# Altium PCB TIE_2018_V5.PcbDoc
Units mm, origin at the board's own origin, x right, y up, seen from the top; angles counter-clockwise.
Board outline 31 x 99 mm, 4 copper layers (T, IN1, IN2, B), stack 0.558 mm thick; 52 components, 39 nets, 169 pads, 161 vias.
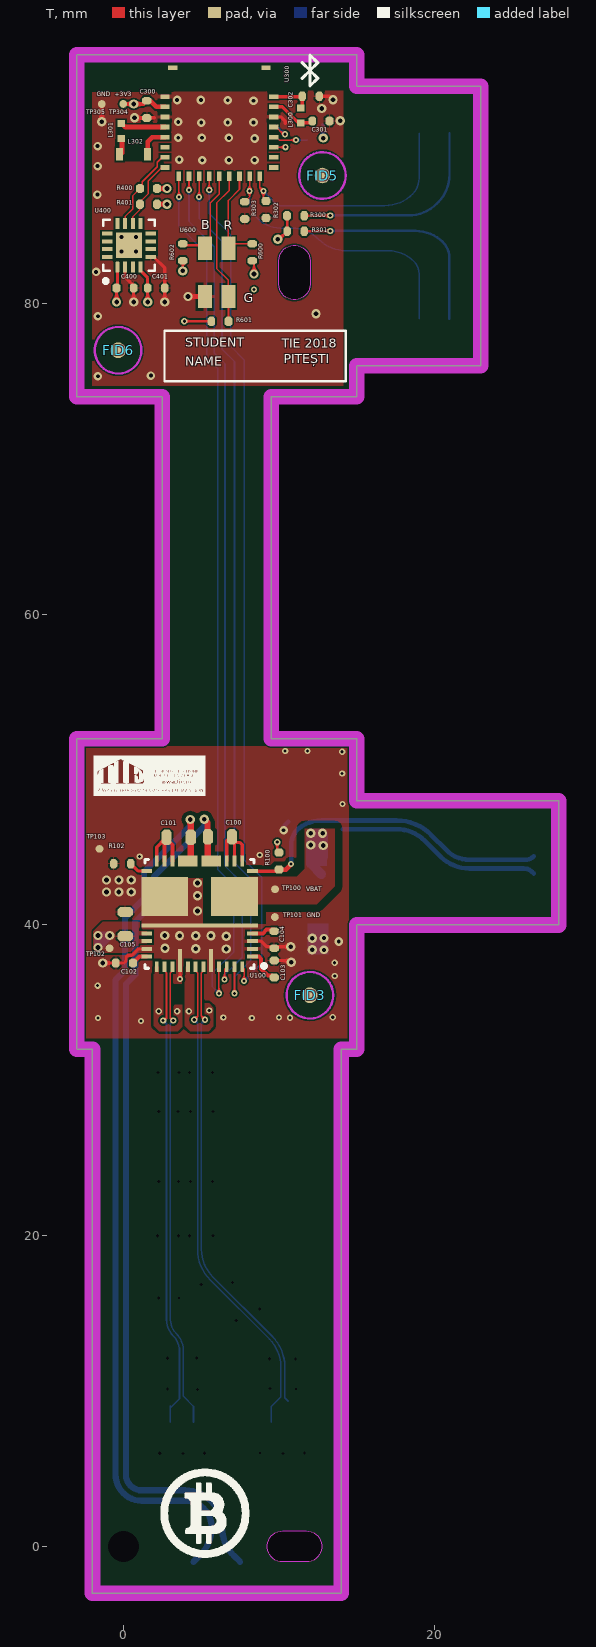
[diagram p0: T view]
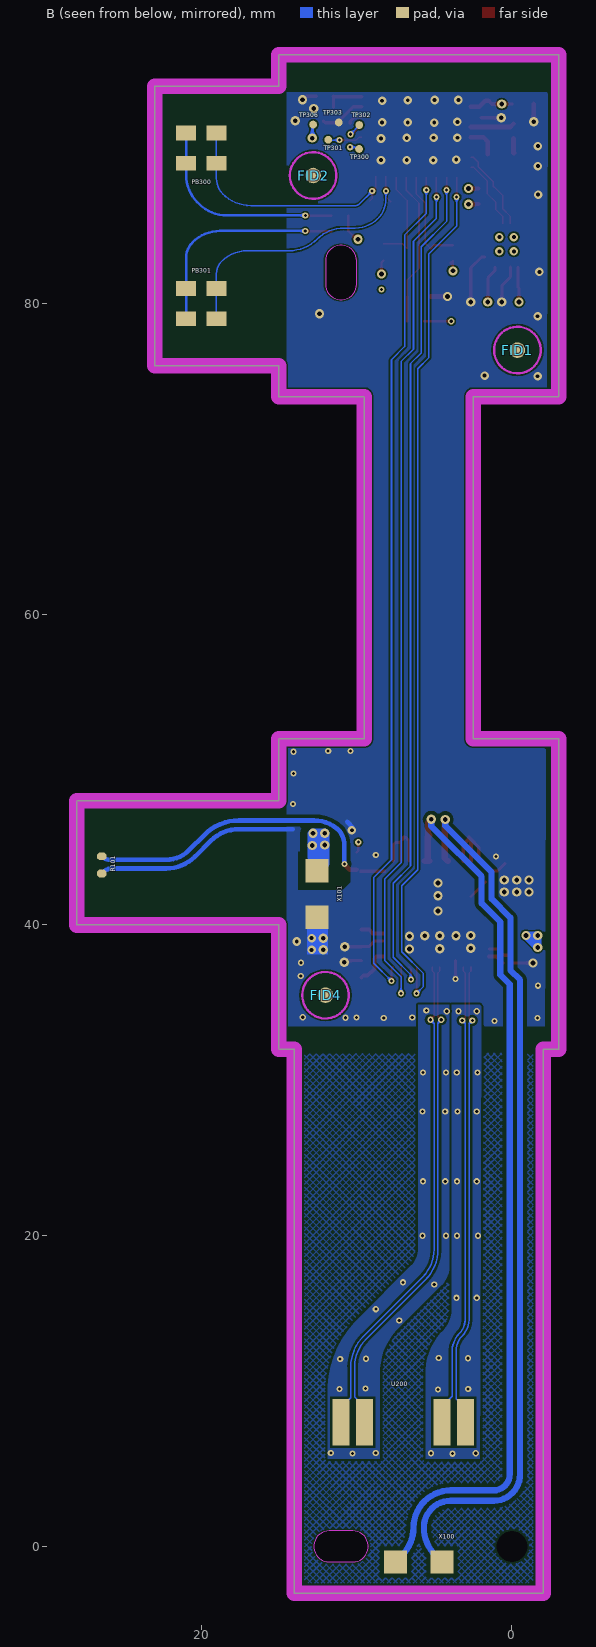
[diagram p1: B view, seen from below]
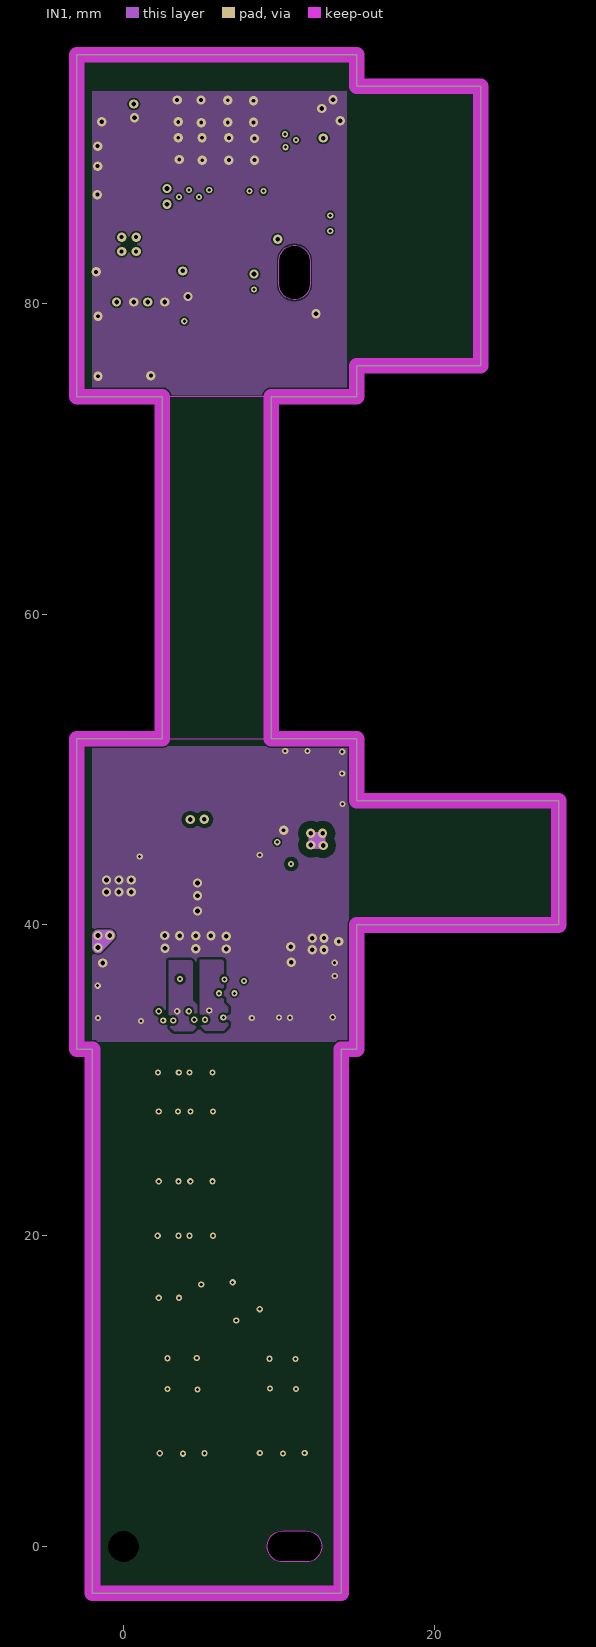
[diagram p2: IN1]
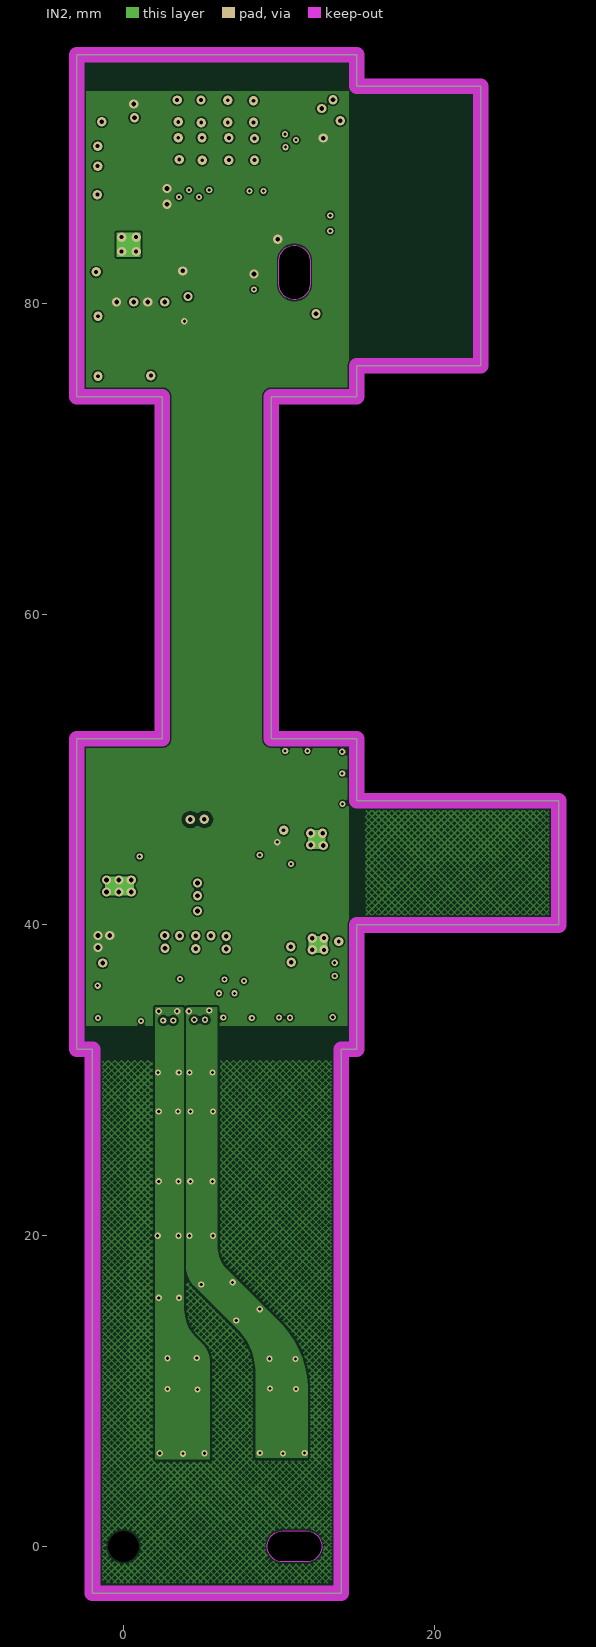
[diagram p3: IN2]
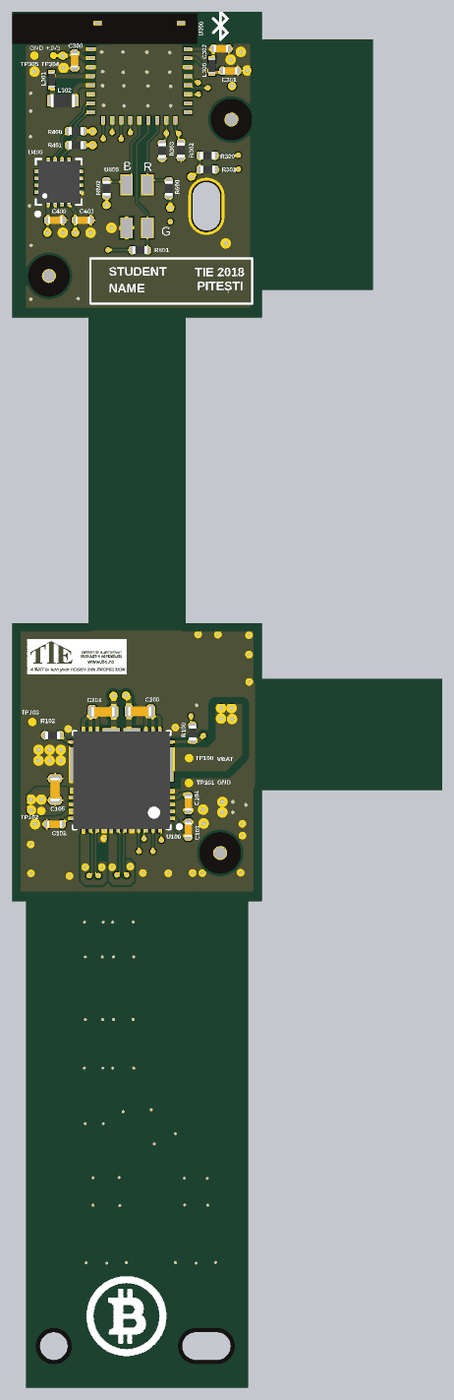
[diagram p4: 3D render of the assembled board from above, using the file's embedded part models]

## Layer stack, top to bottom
Top Solder: solder mask 0.025, Solder Resist, Dk 3.6
T: signal copper 0.0262
Dielectric1: prepreg 0.128, FR-4, Dk 4.2
IN1: signal copper 0.0062
Dielectric 2: core 0.237, FR4, Dk 4.2
IN2: signal copper 0.0062
Dielectric 3: prepreg 0.128, FR4, Dk 4.2
B: signal copper 0.0262
Bottom Solder: solder mask 0.025, Solder Resist, Dk 3.6

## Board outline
-3,32 -2,32 -2,-3 14,-3 14,32 15,32 15,40 28,40 28,48 15,48 15,52 9.5,52 9.5,74 15,74 15,76 23,76 23,94 15,94 15,96 -3,96 -3,74 2.5,74 2.5,52 -3,52
cut-out: 12,82.75 12,81.25 cw(c11,81.25) 10,81.25 10,82.75 cw(c11,82.75)
cut-out: 10.25,1 11.75,1 cw(c11.75,0) 11.75,-1 10.25,-1 cw(c10.25,0)
cut-out: 12,82.75 12,81.25 cw(c11,81.25) 10,81.25 10,82.75 cw(c11,82.75)
cut-out: 10.25,1 11.75,1 cw(c11.75,0) 11.75,-1 10.25,-1 cw(c10.25,0)
board region "Layer Stack Region 1": 15,52 15,32 -3,32 -3,52
board region "Layer Stack Region 1": 14,32 14,-3 -2,-3 -2,32
board region "Layer Stack Region 1": 15,48 28,48 28,40 15,40
board region "Layer Stack Region 1": 15,74 9.5,74 -3,74 -3,96 15,96
board region "Layer Stack Region 1": 9.5,74 9.5,52 2.5,52 2.5,74
board region "Layer Stack Region 1": 15,94 23,94 23,76 15,76

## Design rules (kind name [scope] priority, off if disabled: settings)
BoardOutlineClearance [All] p1 off: gap=0.5 ignorepadtopadclearanceinfootprint=FALSE
Clearance Clearance_VBAT [InNet('VBAT') vs InNet('GND')] p1: gap=0.5 ignorepadtopadclearanceinfootprint=FALSE
Clearance Clearance_NTC [InNet('TS_CTRL') vs InNet('GND')] p2: gap=0.25 ignorepadtopadclearanceinfootprint=FALSE
Clearance Clearance_WPC2WPC [InNetClass('COIL') vs InNetClass('COIL')] p3: gap=0.25 ignorepadtopadclearanceinfootprint=FALSE
Clearance Clearance_WPC_AC [InNetClass('COIL')] p4: gap=0.25 ignorepadtopadclearanceinfootprint=FALSE
Clearance Clearance_RF [InNetClass('RF')] p5: gap=0.3 ignorepadtopadclearanceinfootprint=FALSE
Clearance Clearance_SHIELD [InNetClass('SHIELD')] p6: gap=0.15 ignorepadtopadclearanceinfootprint=FALSE
Clearance Clearance_100 [All] p7: gap=0.1 ignorepadtopadclearanceinfootprint=FALSE
ComponentClearance 3d-Body-2-3d-Body [(ObjectKind = '3D Body') And (Layer = 'Mechanical 3') vs (ObjectKind = '3D Body') And (Layer = 'Mechanical 3')] p1: gap=-1000 collisioncheckmode=3 verticalgap=2540 showdistances=FALSE
ComponentClearance TP-2-TP [HasFootprint('TESTPOINT_500') vs HasFootprint('TESTPOINT_500')] p2: gap=0.5 collisioncheckmode=3 verticalgap=0.1 showdistances=TRUE
ComponentClearance 3d-Body-2-PCB [(ObjectKind = '3D Body') And (Layer = 'Mechanical 3')] p3: gap=-1000 collisioncheckmode=3 verticalgap=2540 showdistances=FALSE
ComponentClearance [All] p4: gap=0.4 collisioncheckmode=3 verticalgap=0.4 showdistances=TRUE
DiffPairsRouting [All] p1: maxlimit=0.5 minlimit=0.15 mostfreqgap=0.15 toplayer_minwidth=0.1 toplayer_maxwidth=0.1 toplayer_prefwidth=0.1 midlayer1_minwidth=0.1 midlayer1_maxwidth=0.1 midlayer1_prefwidth=0.1 midlayer2_minwidth=0.1 midlayer2_maxwidth=0.1 midlayer2_prefwidth=0.1 bottomlayer_minwidth=0.1 bottomlayer_maxwidth=0.1 bottomlayer_prefwidth=0.1 maxuncoupledlength=2
HoleSize [All] p1: absolutevalues=TRUE maxlimit=4 minlimit=0.16 maxpercent=80.000 minpercent=20.000
HoleToHoleClearance [All] p1: gap=0.45 allowstackedmicrovias=TRUE
MinimumAnnularRing [All] p1: minimumring=0.05
MinimumSolderMaskSliver [All] p1: minsoldermaskwidth=0.075
PasteMaskExpansion PasteMaskExpansion-050 [All] p1: expansion=-0.05
PolygonConnect Mid_PAD [InPadClass('Mid_PAD')] p1: connectstyle=Relief reliefconductorwidth=0.25 reliefentries=4 polygonreliefangle="90 Angle" airgapwidth=0.15
PolygonConnect TEST_POINTS [HasFootprint('TESTPOINT_500')] p2: connectstyle=Direct reliefconductorwidth=0.254 reliefentries=4 polygonreliefangle="90 Angle" airgapwidth=0.254
PolygonConnect BigPAD [InPadClass('Big_PAD')] p3: connectstyle=Direct reliefconductorwidth=0.254 reliefentries=4 polygonreliefangle="90 Angle" airgapwidth=0.254
PolygonConnect ThermalVias [IsVia] p4: connectstyle=Direct reliefconductorwidth=0.254 reliefentries=4 polygonreliefangle="90 Angle" airgapwidth=0.254
PolygonConnect [All] p5: connectstyle=Relief reliefconductorwidth=0.1 reliefentries=4 polygonreliefangle="90 Angle" airgapwidth=0.1
RoutingCorners [All] p1 off: cornerstyle=45-Degree minsetback=2.54 maxsetback=2.54
RoutingVias [All] p1: holewidth=0.2 width=0.4 viastyle="Through Hole" minholewidth=0.2 minwidth=0.4 maxholewidth=0.3 maxwidth=0.6
ShortCircuit NoNet [Not InAnyNet vs Not InAnyNet] p1: allowed=TRUE
ShortCircuit [All] p2: allowed=FALSE
SilkToSilkClearance [All] p1: silktosilkclearance=0.2
SilkToSolderMaskClearance [IsPad] p1: minsilkscreentomaskgap=0.075 clearancetoexposedcopper=TRUE
SolderMaskExpansion Encrouched_Via [IsVia] p1: expansion=-0.025
SolderMaskExpansion SolderMaskExpansion_075 [All] p2: expansion=0.075
Width Width_NTC [InNet('TS_CTRL')] p1: maxlimit=0.3 minlimit=0.3 preferedwidth=0.3
Width Width_100 [All] p2: maxlimit=2 minlimit=0.1 preferedwidth=0.1
20 further rules are at their usual default settings.

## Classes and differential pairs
net class COIL: AC1 AC2
pad class Mid_PAD: C109-1 C110-1 C111-1 C111-2 C500-2 U100-2 U100-3 U100-33 U100-34 U100-37 U100-41 U300-15 U300-18 U300-20 U400-1 U600-3
component class TIE_2018_Wearable_V5: C100 C101 C102 C103 C104 C105 C300 C301 C302 C400 C401 L300 L301 L302 PB300 PB301 PCB910 R100 R101 R102 R300 R301 R302 R303 R400 R401 R600 R601 R602 TP100 TP101 TP102 TP103 TP300 TP301 TP302 TP303 TP304 TP305 TP306 U100 U200 U300 U400 U600 X100 X101
pad class Big_PAD: U100-4 U100-5 U100-26 U100-32 U100-35 U100-40 U100-44 X101-2
differential pair TX: +TX_P -TX_N
differential pair RX: +RX_P -RX_N

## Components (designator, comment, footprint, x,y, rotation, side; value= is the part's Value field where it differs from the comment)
C100 "10nF" CAPC1608_0603H080 6.2,45.669 r0 top
C101 "10nF" CAPC1608_0603H080 3.547,45.638 r180 top
C102 "100nF" CAPC1005_0402H050 0.05,37.55 r0 top
C103 "100nF" CAPC1005_0402H050 9.695,37.165 r270 top
C104 "100nF" CAPC1005_0402H050 9.695,39.05 r90 top
C105 "4.7uF" CAPC1608_0603H080 0.1,40.05 r270 top
C300 "100nF" CAPC1005_0402H050 1.5,92.5 r270 top
C301 "DNP" CAPC1005_0402H050 12.7,91.75 r180 top
C302 "1pF" CAPC1005_0402H050 12.05,93.339 r180 top
C400 "100nF" CAPC1005_0402H050 0.1,81 r0 top
C401 "100nF" CAPC1005_0402H050 2.1,81 r0 top
FID1 "FIDUCIAL_MARK" Fiducial_MARK -0.351,77.005 r180 bottom
FID2 "FIDUCIAL_MARK" Fiducial_MARK 12.8,88.24 r180 bottom
FID3 "FIDUCIAL_MARK" Fiducial_MARK 11.991,35.477 r0 top
FID4 "FIDUCIAL_MARK" Fiducial_MARK 12.002,35.479 r180 bottom
FID5 "FIDUCIAL_MARK" Fiducial_MARK 12.8,88.24 r0 top
FID6 "FIDUCIAL_MARK" Fiducial_MARK -0.353,76.993 r0 top
L300 "1.1nH" INDC1005_0402H050 11.4,92.1 r90 top
L301 "10nH" INDC1005_0402H050 -0.15,91.106 r90 top
L302 "10uH" INDC1608_0603H102 0.65,89.6 r180 top
PB300 "TIE2018_PB" TIE_2018_PUSH_2.5X2.5 20,90 r0 bottom
PB301 "TIE2018_PB" TIE_2018_PUSH_2.5X2.5 20,80 r0 bottom
R100 "10k" RESC1005_0402H035 10,44.115 r90 top
R101 "10K" RESC1005_0402H035 26.4,43.867 r270 bottom
R102 "3.83k" RESC1005_0402H035 -0.088,43.95 r0 top
R300 "4K7" RESC1005_0402H035 11.076,85.65 r0 top
R301 "10k" RESC1005_0402H035 11.079,84.65 r0 top
R302 "4K7" RESC1005_0402H035 9.162,86.05 r270 top
R303 "4K7" RESC1005_0402H035 7.8,86 r270 top
R400 "10k" RESC1005_0402H035 1.6,87.4 r180 top
R401 "10k" RESC1005_0402H035 1.6,86.4 r180 top
R600 "100R" RESC1005_0402H035 8.289,83.3 r90 top
R601 "100R" RESC1005_0402H035 6.2,78.85 r0 top
R602 "100R" RESC1005_0402H035 3.8,83.3 r90 top
TP100 "0.5mm" TESTPOINT_500 9.75,42.3 r0 top
TP101 "0.5mm" TESTPOINT_500 9.74,40.51 r0 top
TP102 "0.5mm" TESTPOINT_500 -0.9,38.5 r0 top
TP103 "0.5mm" TESTPOINT_500 -1.55,44.9 r0 top
TP300 "0.5mm" TESTPOINT_500 9.84,89.95 r90 bottom
TP301 "0.5mm" TESTPOINT_500 11.824,90.544 r0 bottom
TP302 "0.5mm" TESTPOINT_500 9.83,91.49 r0 bottom
TP303 "0.5mm" TESTPOINT_500 11.15,91.659 r0 bottom
TP304 "0.5mm" TESTPOINT_500 -0.02,92.85 r0 top
TP305 "0.5mm" TESTPOINT_500 -1.4,92.84 r0 top
TP306 "0.5mm" TESTPOINT_500 12.799,91.519 r270 bottom
U100 "TIE_2018_WPC_AFE" TIE2018_WPC-AFE 4.889,40.713 r180 top
U200 "DCM03" DCM03 7,7 r0 bottom
U300 "TIE2018_SoC" TIE2018-SOC 6.162,91.684 r0 top
U400 "TIE2018_DIG_MIC_GYRO" QFN16_P500_3000X3000X750_L 0.35,83.75 r90 top
U600 "TIE2018_RGB" PLCC4_LED 6,82 r180 top
X100 "PADS 1.5x1.5mm" "Contact Pads" 6,-1 r180 bottom
X101 "Header 2" "Contact Pads" 12.55,42 r270 bottom

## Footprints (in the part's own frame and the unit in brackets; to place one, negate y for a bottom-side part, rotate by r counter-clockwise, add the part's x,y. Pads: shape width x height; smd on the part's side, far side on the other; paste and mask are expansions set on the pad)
CAPC1005_0402H050 [mm] "Chip Capacitor, 2-Leads, Body 1.00x0.50mm, IPC Low Density"
  oct 0.5x0.6 smd paste-0.05: 1(-0.55,0) 2(0.55,0)
  body extent -0.53,-0.28 0.53,0.28, height 0.5
CAPC1608_0603H080 [mm] "Chip Capacitor, 2-Leads, Body 1.60x0.60mm, IPC Low Density"
  oct 0.65x1 smd paste-0.05: 1(-0.775,0) 2(0.775,0)
  body extent -0.85,-0.35 0.85,0.35, height 0.8
"Contact Pads" [mm]
  rect 1.5x1.5 smd paste-0.05 mask+0.05: 1(-1.5,0) 2(1.5,0)
DCM03 [mm]
  rect 1.1x3 smd: 1(-4,-1) 2(-2.5,-1) 3(2.5,-1) 4(4,-1)
  body extent -4.9,-2.15 4.9,2.15, height 1.2
Fiducial_MARK [mm]
  round 1 smd mask+1: FID(0,0)
  T pour cut-out: 0,0
  T keep-out circle w0.15: c0,0 r1.5
INDC1005_0402H050 [mm] "Chip Inductor, 2-Leads, Body 1.00x0.50mm, IPC Low Density"
  rect 0.45x0.5 smd paste-0.05: 1(-0.475,0) 2(0.475,0)
  body extent -0.55,-0.26 0.55,0.26, height 0.5
INDC1608_0603H102 [mm] "Chip Inductor, 2-Leads, Body 1.60x0.80mm, IPC Low Density"
  rect 0.45x0.8 smd: 1(-0.9,0) 2(0.9,0)
  body extent -0.87,-0.48 0.87,0.48, height 1.02
PLCC4_LED [mm]
  rect 0.9x1.5 smd: 1(-0.75,1.55) 2(-0.75,-1.55) 3(0.75,1.55) 4(0.75,-1.55)
  body extent -1.4,-1.75 1.4,1.75, height 2.15
QFN16_P500_3000X3000X750_L [mm] "QFN, 16-Leads, Body 3.00x3.00mm, Pitch 0.50mm, Thermal Pad 2.50x2.50mm, IPC High Density"
  rrect50% 0.7x0.25 smd: 1(-1.4,0.75)
  rect 0.7x0.25 smd: 2(-1.4,0.25) 3(-1.4,-0.25) 4(-1.4,-0.75) 9(1.4,-0.75) 10(1.4,-0.25) 11(1.4,0.25) 12(1.4,0.75)
  rect 0.25x0.7 smd: 5(-0.75,-1.4) 6(-0.25,-1.4) 7(0.25,-1.4) 8(0.75,-1.4) 13(0.75,1.4) 14(0.25,1.4) 15(-0.25,1.4) 16(-0.75,1.4)
  rrect0% 1.65x1.65 smd: MP(0,0)
  silkscreen extent -2.42,-1.65 1.65,1.65, body extent -1.55,-1.55 1.55,1.55, height 0.75
RESC1005_0402H035 [mm] "Chip Resistor, 2-Leads, Body 1.00x0.50mm, IPC Low Density"
  oct 0.5x0.6 smd paste-0.05 mask+0.05: 1(-0.55,0) 2(0.55,0)
  body extent -0.53,-0.28 0.53,0.28, height 0.35
TESTPOINT_500 [mm]
  round 0.5 smd paste-5 mask+0.05: 1(0,0)
TIE2018-SOC [mm]
  rect 0.3x0.6 smd paste-0.05 mask+0.05: 1(-2.6,-3.5) 2(-1.95,-3.5) 3(-1.3,-3.5) 4(-0.65,-3.5) 5(0,-3.5) 6(0.65,-3.5) 7(1.3,-3.5) 8(1.95,-3.5) 9(2.6,-3.5)
  rect 0.6x0.3 smd paste-0.05 mask+0.05: 10(3.5,-2.925) 11(3.5,-2.275) 12(3.5,-1.625) 13(3.5,-0.975) 14(3.5,-0.325) 15(3.5,0.325) 16(3.5,0.975) 17(3.5,1.625) 18(-3.5,1.625) 19(-3.5,0.975) 20(-3.5,0.325) 21(-3.5,-0.325) 22(-3.5,-0.975) 23(-3.5,-1.625) 24(-3.5,-2.275) 25(-3.5,-2.925) 26(-3,3.5) 27(3,3.5)
  T pour cut-out: -3.496,4 3.504,4 3.504,2 -3.496,2
  body extent -3.5,-3.5 3.5,4, height 1
TIE2018_WPC-AFE [mm]
  rect 0.7x0.25 smd mask+0.1: 1(-3.4,2.75) 12(-3.4,-2.75) 25(3.4,-2.75) 36(3.4,2.75)
  rect 0.7x0.25 smd: 2(-3.4,2.25) 3(-3.4,1.75) 4(-3.4,1.25) 33(3.4,1.25) 34(3.4,1.75) 35(3.4,2.25)
  rect 3x2.5 smd: 5(-2.25,-1.125) 26(2.25,-1.125)
  rect 0.25x0.7 smd mask+0.1: 13(-2.75,-3.4) 24(2.75,-3.4) 37(2.75,3.4) 48(-2.75,3.4)
  rect 0.25x0.7 smd: 14(-2.25,-3.4) 15(-1.75,-3.4) 22(1.75,-3.4) 23(2.25,-3.4) 38(2.25,3.4) 39(1.75,3.4) 41(0.75,3.4) 42(0.25,3.4) 43(-0.25,3.4) 45(-1.25,3.4) 46(-1.75,3.4) 47(-2.25,3.4)
  rect 1.25x0.7 smd: 16(-0.75,-3.4) 19(0.75,-3.4)
  rect 7.5x0.25 smd: 32(0,0.75)
  rect 0.25x1.5 smd: 40(1.25,3) 44(-0.75,3)
  silkscreen extent -4.28,-3.5 3.5,3.5, body extent -3.5,-3.5 3.5,3.5, height 0.75
TIE_2018_PUSH_2.5X2.5 [mm]
  rect 1.3x0.95 smd: 1(0.975,-0.975) 1(0.975,0.975) 2(-0.975,-0.975) 2(-0.975,0.975)
  body extent -1.41,-1.25 1.4,1.25, height 0.35

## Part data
C100 C101 C102 C103 C104 C105 C300 C301 C302 C400 C401: library part Cap
L300 L301 L302: library part Inductor
PB300 PB301: library part PushButton
R100 R102 R300 R301 R302 R303 R400 R401 R600 R601 R602: library part Res
R101: library part Res_Thermistor
TP100 TP101 TP102 TP103 TP300 TP301 TP302 TP303 TP304 TP305 TP306: library part TestPoint_0500
U100: library part TIE2018_WPC_AFE
U200: library part TIE2018_PULSE
X100: library part "Header 2"

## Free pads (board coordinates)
  round 0 hole 2 unplated mask+1.3: ORIGIN(0,0)
  oval 3.5x2 hole 2 slot 3.5 at 0 deg unplated mask+0.3: SLOT1(11,0)
  oval 2x3.5 hole 2 slot 3.5 at 90 deg unplated mask+0.3: SLOT1(11,82)

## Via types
v1: diameter 0.6, hole 0.3, T to B, 49 vias
v2: diameter 0.4, hole 0.2, T to B, 45 vias
v3: diameter 0/0.4/0.4/0.4 (per signal layer), hole 0.2, T to B, 36 vias
v4: diameter 0.55/0.6/0.6/0.55 (per signal layer), hole 0.25, T to B, 31 vias

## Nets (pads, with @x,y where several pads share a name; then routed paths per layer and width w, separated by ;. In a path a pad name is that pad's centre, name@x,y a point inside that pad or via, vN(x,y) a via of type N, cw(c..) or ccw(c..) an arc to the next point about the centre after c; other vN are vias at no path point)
+3V3: C105.2 C300.1 C400.1 C401.1 R100.2 R300.1 R301.1 R400.1 R401.1 R600.1 R601.1 R602.1 TP102.1 TP304.1 TP306.1 U100.33 U100.34 U300.19 U400.1 U400.4 | length 21.1
  T w0.15: v1(3.8,82.1) 3.8,82.45 ; v2(3.91,78.861) 4.889,78.861 ; 4.9,78.85 4.889,78.861 ; R601.1 5.639,78.861 4.889,78.861 ; R600.1 8.4,82.639 v1(8.4,81.9) ; v2(9.89,45.33) 9.89,44.775 R100.2 ; v1@10.079,84.2 R301.1 10.529,85.647 R300.1 ; 3.8,82.45 3.95,82.6 R602.1 3.8,82.45
  T w0.2: v1(-0.45,80.1) C400.1 -0.4,81.05 U400.1 ; U400.4 1.1,82.1 1.55,81.65 C401.1 v1(1.55,80.1)
  T w0.203: TP304.1 -0.01,92.84 v1(0.65,92.84)
  T w0.25: v1(0.65,92.84) 1.29,92.84 C300.1 ; R401.1 v1(2.8,86.4) ; R400.1 v1(2.8,87.4)
  T w0.3: C300.1 1.723,93.05 2.114,92.659 U300.19
  IN1 w0.75: v1(-1.65,38.55) -1.263,38.95 v1(-0.9,39.325) v1(-1.65,39.325) v1(-1.65,38.55)
  B w0.203: TP306.1 12.85,91.468 v1(12.85,90.65)
  B w0.5: v1(-1.65,38.55) -0.9,39.3 v1(-0.9,39.325) v1(-1.65,39.325) v1(-1.65,38.55)
  other v1: 9.914,84.132
AC1: C100.1 U100.16 X100.1 | length 58
  T w0.4: v1(5.2,46.8) 5.4,46.6 5.4,45.834 5.33,45.764 C100.1 5.425,44.208 5.33,44.113 U100.16
  B w0.4: 4.819,45.99 4.819,45.981 ; v1@5.2,46.576 5.2,46.363 4.819,45.981 ; v1@5.2,46.785 v1(5.2,46.8) ; X100.1 7.084,-0.584 cw(c8.88,1.212) 6.34,1.212 ccw(c3.942,1.212) 3.942,3.61 1.17,3.61 cw(c1.17,4.63) 0.15,4.63 0.15,36.19 0.75,36.79 0.75,40.195 1.96,41.405 1.96,43.123 4.819,45.981
AC2: C101.1 U100.19 X100.2 | length 57.6
  T w0.4: U100.19 4.322,44.296 C101.1 4.322,46.763 v1(4.3,46.785)
  B w0.4: v1(4.3,46.785) 4.3,46.382 1.31,43.392 1.31,41.675 0.1,40.465 0.1,37.088 -0.52,36.468 -0.52,4.63 ccw(c1.17,4.63) 1.17,2.94 3.952,2.94 cw(c3.952,1.222) 5.67,1.222 cw(c3.13,1.222) 4.926,-0.574 X100.2
ANTIN: C302.2 L300.2 U300.17 | length 2.6
  T w0.22: U300.17 11.47,93.309 C302.2@11.489,93.328 ; L300.2@11.489,92.626 C302.2@11.489,93.328 ; C302.2 C302.2@11.489,93.328 ; C302.2@11.5,93.35 11.489,93.339 C302.2@11.489,93.328
ANTOUT: C301.2 L300.1 U300.16 | length 3
  T w0.22: U300.16 10.209,92.659 11.243,91.625 L300.1 12.025,91.625 C301.2
BOOT1: C100.2 U100.13 U100.14 U100.15 | length 5.1
  T w0.2: U100.15 6.639,45.428 6.88,45.669 C100.2@6.975,45.574 ; C100.2 C100.2@6.975,45.574 ; U100.14 C100.2@7.139,45.41 ; U100.13 7.639,45.161 7.5,45.3 7.249,45.3 C100.2@7.139,45.41 ; C100.2@6.975,45.574 C100.2@7.139,45.41
BOOT2: C101.2 U100.22 U100.23 U100.24 | length 4.9
  T w0.25: U100.24 2.139,45.005 C101.2@2.639,45.505 ; U100.23 C101.2@2.639,45.505 ; U100.22 3.139,45.161 2.772,45.528 C101.2 C101.2@2.639,45.505
DI_PB_1: PB300.2 R302.1 U300.9 | length 16
  T w0.1: U300.9 8.762,87.473 v2(9,87.235) 9,86.762 R302.1
  B w0.1: v2(9,87.235) 9.818,86.417 ccw(c10.1,86.699) 10.1,86.3 16.807,86.3 ccw(c16.807,88.84) 18.603,87.044 ccw(c17.583,88.064) 19.025,88.064 19.025,89.025 PB300.2@19.025,90.975
DI_PB_2: PB301.2 R303.1 U300.8 | length 18.3
  T w0.1: R303.1 8.112,86.862 v2(8.112,87.25) U300.8
  B w0.1: v2(8.112,87.25) 8.112,86.749 ccw(c9.949,86.749) 8.65,85.45 ccw(c10.078,86.878) 10.078,84.859 10.823,84.859 cw(c10.823,82.419) 12.548,84.144 ccw(c14.344,85.94) 14.344,83.4 17.01,83.4 cw(c17.01,81.01) 18.7,82.7 cw(c17.915,81.915) 19.025,81.915 19.025,80.975 PB301.2@19.025,79.025
GND: C102.1 C103.1 C104.1 C105.1 C300.2 C301.1 C302.1 C400.2 C401.2 R101.2 R102.1 R302.2 R303.2 TP101.1 TP103.1 TP303.1 TP305.1 U100.2 U100.3 U100.26 U100.32 U100.35 U100.40 U100.44 U300.15 U300.18 U300.20 U400.2 U400.5 U600.3 X101.2 | length 35.6
  T w0.2: v1(-1.35,37.55) C102.1 0.025,37.55 0.15,37.675 0.15,37.933 0.267,38.05 0.525,38.05 0.938,38.463 U100.35 ; U400.2 0.1,81.7 0.65,81.15 C400.2 v1(0.65,80.1) ; U100.26@1.707,42.77 U100.26 ; U400.5 1.95,83 2.65,82.3 C401.2 v1(2.65,80.1) ; v2(3.639,36.519) U100.40 ; U100.3 8.857,38.963 9.215,38.605 9.695,38.605 9.7,38.6 v1(10.755,38.6) ; C103.1 9.705,37.705 10.695,37.705 v1(10.8,37.6)
  T w0.22: v1(0.7,91.95) C300.2 1.967,91.95 ; U300.15 10.123,92.009 10.399,91.733 10.399,91.6 ; C302.1@12.6,93.35 12.61,93.34 13.25,93.34 v1(13.48,93.11)
  T w0.3: TP305.1 -1.396,92.836 v1(-1.396,91.694) ; v4@3.429,93.122 v4(3.45,93.1) ; v1(4.15,80.45) U600.3
  B w0.3: v4(10.3,46.1) cw(c10.904,46.1) 10.477,46.527 10.6,46.65 ; 14.1,46.165 17.589,46.165 cw(c17.589,43.625) 19.385,45.422 20.403,44.403 ccw(c22.249,46.249) 22.249,43.639 25.75,43.639 cw(c25.75,42.847) 26.31,43.407 R101.2
  B w0.6: v1(12.15,38.4) v1(12.15,39.15)
  other v1: 4.639,38.463 6.6,38.45 2.662,38.5 6.6,39.275 3.605,39.3 4.639,39.3 5.622,39.3 2.65,39.325 4.76,40.9 4.76,41.875 -1.1,42.125 -0.3,42.125 0.5,42.125 4.76,42.7 -1.1,42.9 -0.3,42.9 0.5,42.9 12.39,79.335 13.95,91.77 12.75,92.55
  other v2: 1.128,33.821 -1.65,34.01 8.256,34.01 6.422,34.037 10,34.037 10.709,34.027 13.465,34.058 -1.668,36.094 13.596,36.721 13.588,37.57 1.035,44.4 8.762,44.5 14.09,47.78 14.07,49.75 14.07,51.15 11.83,51.19 10.4,51.2
  other v4: 12.9,38.4 13.851,38.938 12.9,39.15 -1.649,75.32 1.758,75.358 -1.649,79.185 -1.763,82.037 -1.687,87.012 -1.666,88.845 5.067,89.221 6.776,89.233 8.429,89.233 3.585,89.268 -1.668,90.131 8.429,90.624 6.776,90.661 3.517,90.674 5.046,90.674 5,91.647 6.709,91.659 8.362,91.659 3.517,91.694 8.362,93.05 4.979,93.1 6.709,93.088
I2C_SCL: R401.2 U300.25 U400.10 | length 4.6
  T w0.1: U400.10 0.6,85.6 1.05,86.05 R401.2 1.05,86.534 1.6,87.084 1.6,87.9 2.459,88.759 U300.25
I2C_SDA: R400.2 U300.24 U400.11 | length 5.4
  T w0.1: U400.11 0.1,85.6 0.6,86.1 0.6,86.95 R400.2 1.2,87.55 1.2,87.838 2.166,88.804 2.166,89.087 2.488,89.409 U300.24
ILIM: R102.2 U100.25 | length 1.2
  T w0.2: R102.2 0.948,43.463 U100.25
LED_B: R602.2 U300.5 U600.4 | length 6.5
  T w0.1: U600.4 5.58,83.88 5.58,86.472 6.162,87.054 U300.5@6.162,88.122
  T w0.15: R602.2@3.8,83.76 5.04,83.76 U600.4
LED_G: R601.2 U300.6 U600.1 | length 9.9
  T w0.1: U600.1 6.75,81.497 5.985,82.262 5.985,86.468 6.812,87.295 U300.6@6.812,88.122
  T w0.15: R601.2 U600.1
LED_R: R600.2 U300.7 U600.2 | length 6.5
  T w0.1: U300.7@7.462,88.122 7.462,87.35 6.75,86.638 U600.2 7.05,83.85 R600.2
NetC102_2: C102.2 U100.36 | length 1.1
  T w0.25: C102.2 1.013,37.963 U100.36
NetC103_2: C103.2 U100.1 | length 2.3
  T w0.25: U100.1 8.717,37.963 8.857,37.823 8.857,37.172 9.29,36.738 9.572,36.738 C103.2
NetC104_2: C104.2 U100.4 | length 1.5
  T w0.25: U100.4 8.968,39.463 9.21,39.705 C104.2@9.695,39.705
NetL301_1: L301.1 L302.2 | length 0.9
  T w0.35: L302.2@-0.122,89.7 -0.1,89.722 L301.1@-0.1,90.625
NetL301_2: L301.2 U300.21 | length 2.9
  T w0.3: L301.2@-0.1,91.575 0.116,91.359 U300.21
NetL302_1: L302.1 U300.22 | length 2.1
  T w0.3: L302.1 1.55,90.426 1.833,90.709 U300.22
NetPB300_1: PB300.1 R300.2 | length 13.5
  T w0.16: R300.2 13.24,85.65 ccw(c13.24,85.735) v2(13.3,85.675)
  B w0.15: v2(13.3,85.675) 18.352,85.675 ccw(c18.352,88.215) 20.148,86.419 20.231,86.502 ccw(c18.435,88.298) 20.975,88.298 20.975,89.025 PB300.1@20.975,90.975
NetPB301_1: PB301.1 R301.2 | length 14.2
  T w0.16: R301.2 13.243,84.65 ccw(c13.243,84.735) v2(13.303,84.675)
  B w0.16: v2(13.303,84.675) 18.799,84.675 cw(c18.799,82.199) 20.55,83.95 cw(c19.524,82.924) 20.975,82.924 20.975,80.975 PB301.1@20.975,79.025
RESET: TP301.1 U300.13 | length 2.2
  T w0.1: U300.13 9.841,90.709 10.029,90.521 v2(11.104,90.521)
  B w0.1: v2(11.104,90.521) 11.801,90.521 TP301.1
RX_N: U100.43 U200.4 | length 30.3
  T w0.1: U100.43 5.139,37.038 5.014,36.913 5.014,34.136 v2(5.25,33.9)
  B w0.1: v2(5.25,33.9) 5.014,33.664 5.014,19.128 ccw(c7.554,19.128) 5.758,17.332 9.563,13.527 cw(c7.59,11.554) 10.38,11.554 10.38,9.565 U200.4@10.595,9.35
RX_P: U100.42 U200.3 | length 31.8
  T w0.1: v2(4.55,33.9) 4.764,34.114 4.764,36.913 4.639,37.038 U100.42
  B w0.1: v2(4.55,33.9) 4.764,33.686 4.764,19.128 ccw(c7.554,19.128) 5.581,17.155 9.386,13.35 cw(c7.59,11.554) 10.13,11.554 10.13,9.64 9.5,9.01 U200.3
RX_REF: U100.41
  other v2: 4.2,34.45 5.512,34.5
  other v3: 10.26,5.98 8.77,6.01 11.658,6.01 11.104,10.13 9.43,10.16 11.06,12.07 9.4,12.08 7.256,14.542 8.762,15.272 5,16.859 7.022,17 4.243,20 5.761,20 4.298,23.5 5.718,23.5 4.3,28 5.761,28 4.243,30.5 5.718,30.5
SPI_CLK: U100.47 U300.3 | length 56.1
  T w0.1: v2@4.862,86.792 v2(4.862,86.855) U300.3@4.862,88.122 ; v2(7.139,35.6) U100.47
  B w0.1: v2(4.862,86.855) 4.862,85.492 6.337,84.017 6.337,77.065 7.139,76.263 7.139,44 8.2,42.939 8.2,37.727 7.139,36.666 v2(7.139,35.6)
SPI_EN: U100.48 U300.4 | length 54.6
  T w0.1: v2(5.512,87.31) U300.4@5.512,88.122 ; U100.48@7.639,37.32 U100.48 7.756,37.196 v2(7.756,36.4)
  B w0.1: v2(5.512,87.31) 5.512,85.804 6.91,84.405 6.91,77.234 7.755,76.389 7.755,44.2 8.9,43.055 8.9,37.544 v2(7.756,36.4)
SPI_SIMO: U100.45 U300.1 | length 56.5
  T w0.1: v2@3.562,86.792 v2(3.562,86.855) U300.1@3.562,88.122 ; v2(6.139,35.6) U100.45
  B w0.1: v2(3.562,86.855) 3.562,84.988 5.344,83.206 5.344,76.522 6.07,75.795 6.07,43.6 6.07,43.552 7.1,42.522 7.1,38.27 5.7,36.87 5.7,36.039 v2(6.139,35.6)
SPI_SOMI: U100.46 U300.2 | length 54.4
  T w0.1: v2(4.212,87.31) U300.2@4.212,88.122 ; v2(6.5,36.5) 6.5,37.174 U100.46
  B w0.1: v2(4.212,87.31) 4.212,85.288 5.843,83.657 5.843,76.825 6.53,76.138 6.53,43.8 7.639,42.691 7.639,37.929 6.53,36.82 6.53,36.53 v2(6.5,36.5)
SWD_CLK: TP300.1 U300.12 | length 1.4
  T w0.1: U300.12 10.419,90.059 v2(10.425,90.065)
  B w0.1: TP300.1 9.955,90.065 v2(10.425,90.065)
SWD_IO: TP302.1 U300.14 | length 1.8
  T w0.1: U300.14 9.817,91.359 10.276,90.9 v2(10.399,90.9)
  B w0.1: TP302.1 9.83,91.469 v2(10.399,90.9)
TS_CTRL: R100.1 R101.1 U100.12 | length 19.5
  T w0.3: R100.1 10.45,43.565 v2@10.8,43.915
  B w0.3: v2(10.785,43.925) 10.785,45.057 cw(c12.543,45.057) 10.9,45.682 cw(c12.543,45.057) 11.09,46.046 cw(c12.732,44.403) 12.732,46.726 17.589,46.726 cw(c17.589,43.625) 19.782,45.818 20.8,44.8 ccw(c22.249,46.249) 22.249,44.2 25.876,44.2 ccw(c25.876,44.942) R101.1
TX_N: U100.38 U200.1 | length 30.3
  T w0.1: v2@2.604,33.85 2.764,34.01 2.764,36.913 2.639,37.038 U100.38
  B w0.1: v2(2.55,33.85) 2.562,33.838 2.764,33.636 2.764,14.604 ccw(c4.264,14.604) 3.203,13.543 cw(c2.245,12.585) 3.6,12.585 ; U200.1 U200.1@3,8.91 ; U200.1@3,9.049 U200.1@3,8.91 ; 3.6,12.785 3.6,12.585 ; U200.1@3,8.91 3.6,9.51 3.6,12.585
TX_P: U100.39 U200.2 | length 30
  T w0.1: U100.39 3.139,37.038 3.014,36.913 3.014,34.01 3.2,33.824 v2(3.2,33.85)
  B w0.1: v2@3.154,33.8 3.014,33.66 3.014,14.604 ccw(c4.264,14.604) 3.38,13.72 cw(c2.245,12.585) 3.85,12.585 3.85,9.66 4.5,9.01 U200.2
TX_REF: U100.37
  other v2: 2.264,34.45 3.45,34.45
  other v3: 3.82,5.97 2.33,6 5.218,6 4.76,10.11 2.82,10.13 2.831,12.11 4.71,12.13 2.264,16 3.562,16 2.193,20 3.53,20 2.264,23.5 3.53,23.5 2.264,28 3.5,28 2.22,30.5 3.557,30.5
VBAT: TP100.1 U100.5 X101.1 | length 5.3
  B w0.6: X101.1@12.736,43.256 12.05,43.942 v1(12.05,45.144) v1(12.05,45.9) v1(12.81,45.9) 12.85,45.86 v1(12.85,45.111) 12.85,44.36 12.81,44.32
pads on no net: FID1.FID FID2.FID FID3.FID FID4.FID FID5.FID FID6.FID U300.10 U300.11 U300.23 U300.26 U300.27 U400.3 U400.6 U400.7 U400.8 U400.9 U400.12 U400.13 U400.14 U400.15 U400.16 U400.MP
copper on no net:
  other v2: 8.403,80.9
  other v4: -0.122,83.352 0.806,83.352 -0.125,84.275 0.806,84.275

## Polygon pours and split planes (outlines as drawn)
no net on IN2 "IN2_NONET_P058" (hatched 45Degree grid 0.3 track 0.1, remove dead copper, pour order 58): -0.125,84.275
no net on IN2 "IN2_NONET_P050" (hatched 45Degree grid 0.3 track 0.1, pour order 50): 13.894,31.25 13.894,-2.83 -2.04,-2.83 -2.04,31.25
no net on IN2 "IN2_NONET_P048" (hatched 45Degree grid 0.3 track 0.1, remove dead copper, pour order 48): 15.561,47.756 27.8,47.735 27.8,40.507 25.76,40.476 15.616,40.476
GND on IN2 "IN2_GND_P038" (solid, remove dead copper, pour order 38): -0.1,42.9
RX_REF on IN2 "IN2_RX_REF_P020" (solid, remove dead copper, pour order 20): 4.01,34.7 6.04,34.7 6.04,19.214 ccw(c7.883,19.214) 6.58,17.91 10.003,14.487 cw(c5.545,10.028) 11.85,10.028 11.85,5.7 8.5,5.7 8.5,11.234 ccw(c4.655,11.234) 7.374,13.952 4.61,16.717 cw(c6.057,18.164) 4.01,18.164
TX_REF on IN2 "IN2_TX_REF_P012" (solid, remove dead copper, pour order 12): 2.05,9.6 2.05,34.7 3.88,34.7 3.88,15.272 ccw(c6.395,15.272) 4.617,13.493 5.023,13.087 cw(c3.749,11.814) 5.55,11.814 5.55,5.62 2.05,5.62
+3V3 on IN2 "IN2_+3V3_P024" (solid, remove dead copper, pour order 24): -2.515,93.68 14.485,93.68 14.485,33.5 -2.515,33.5
GND on IN2 "IN2_GND_P032" (solid, remove dead copper, pour order 32): -2,52
no net on IN1 "IN1_NONET_P044" (hatched Horizontal grid 0.5 track 0.1, remove dead copper, pour order 44): 23.54,51.01
RX_REF on IN1 "IN1_RX_REF_P016" (solid, remove dead copper, pour order 16): 4.9,37.765 6.45,37.765 6.45,35 6.75,34.7 6.75,33.5 6.45,33.2 5.25,33.2 4.9,33.55
TX_REF on IN1 "IN1_TX_REF_P010" (solid, remove dead copper, pour order 10): 2.9,37.715 4.45,37.715 4.45,35.162 4.75,34.862 4.75,33.45 4.45,33.15 3.25,33.15 2.9,33.5
GND on IN1 "IN1_GND_P028" (solid, remove dead copper, pour order 28): -2,51.5 14.485,51.5 14.485,32.5 -2,32.5
GND on IN1 "IN1_GND_P026" (solid, remove dead copper, pour order 26): -2,93.68 -2,74 14.351,74 14.351,93.68
GND on T "T_GND_P040" (solid, remove dead copper, pour order 40): -2.015,93.597 -2.015,74.7 14.15,74.7 14.15,93.684 10.9,93.684
RX_REF on T "T_RX_REF_P018" (solid, remove dead copper, pour order 18): 3.931,37.737 5.481,37.737 5.481,34.987 5.781,34.686 5.781,33.472 5.481,33.172 4.281,33.172 3.931,33.522
TX_REF on T "T_TX_REF_P008" (solid, remove dead copper, pour order 8): 1.94,37.73 3.49,37.73 3.49,35.177 3.79,34.877 3.79,33.465 3.49,33.165 2.29,33.165 1.94,33.515
+3V3 on T "T_+3V3_P006" (solid, remove dead copper, pour order 6): -1.938,38.432 -1.707,38.2 1.25,38.2 1.7,38.65 2.95,38.65 2.95,39.705 2.036,39.705 1.541,40.2 -1.35,40.2 -1.938,39.612
VBAT on T "T_VBAT_P004" (solid, remove dead copper, pour order 4): 8.1,43.1 11.15,43.1 11.66,43.61 11.66,46.2 13.58,46.2 13.58,42.49 12.44,41.35 8.1,41.35
GND on T "T_GND_P034" (solid, remove dead copper, pour order 34): -2.517,51.491 14.485,51.491 14.485,32.72 -2.624,32.72
no net on B "B_NONET_P056" (hatched 45Degree grid 0.3 track 0.1, remove dead copper, pour order 56): -1.7,31.74 -1.7,-2.81 14.04,-2.81 14.04,31.68
GND on B "B_GND_P036" (solid, remove dead copper, pour order 36): -2.125,33.485 14.485,33.485 14.485,93.6 -2.312,93.6
RX_REF on B "B_RX_REF_P022" (solid, remove dead copper, pour order 22): 4,34.85 6.04,34.85 6.04,19.172 ccw(c7.613,19.172) 6.501,18.059 9.941,14.619 cw(c5.333,10.011) 11.85,10.011 11.85,5.65 8.5,5.65 8.5,11.234 ccw(c4.573,11.234) 7.35,14.01 4.618,16.742 cw(c6.111,18.234) 4,18.234
TX_REF on B "B_TX_REF_P014" (solid, remove dead copper, pour order 14): 1.985,34.85 3.88,34.85 3.88,15.219 ccw(c5.786,15.219) 4.438,13.872 cw(c1.754,11.188) 5.55,11.188 5.55,5.63 2.066,5.63 2.05,11.14 2.05,11.28
no net on B "B_NONET_P002" (solid, remove dead copper, pour order 2): 14.915,38.08
+3V3 on B "B_+3V3_P000" (solid, remove dead copper, pour order 0): 13.81,45.9

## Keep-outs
T:
  the board outline again, w1
IN1:
  rectangle: 2.5,52 9.5,74
  lines w1: -3,32 -2,32 -2,-3 14,-3 14,32 15,32 15,40 28,40 28,48 15,48 15,52 9.5,52 9.5,74 15,74 15,76 23,76 23,94 15,94 15,96 -3,96 -3,74 2.5,74 2.5,52 -3,52 -3,32
IN2:
  the board outline again, w1
B:
  the board outline again, w1

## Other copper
T:
  rectangle net TS_CTRL: 8.112,43.35 9.8,43.565
  pour cut-out: -0.5,91.25 -0.55,89.15 1.25,89.159 1.275,90.85 3.016,90.9 3.016,91.25
  pour cut-out: 5.27,34.96 5.56,34.96 5.56,35.04 5.2,35.04 5.2,34.95
  pour cut-out: 3.218,34.87 3.218,36.2 3.79,36.2 3.79,34.86
  pour cut-out: 0.8,44.656
  pour cut-out: 1.2,43.75 1.2,43.05 5.7,43.05 5.7,43.75
  pour cut-out: 6.412,88.521 7.3,88.521 7.3,88.244 6.4,88.244
  pour cut-out: 9.324,90.393 9.262,90.393 9.262,90.121 9.324,90.121
  pour cut-out: 9.319,91.4 9.257,91.4 9.257,89.25 9.319,89.25
  pour cut-out: 3.062,88.972 3,88.972 3,88.7 3.062,88.7
IN1:
  rectangle net VBAT: 11.894,44.896 13,46
IN2:
  rectangle: -0.45,83 1.1,84.565
  rectangle net VBAT: 11.883,44.9 13.006,46.1
  rectangle net GND: 11.896,38.2 13.114,39.3
  rectangle net GND: -1.2,41.9 0.656,43.136
B:
  region net GND: 13.2,40.1 11.85,40.1 11.85,38.1 13.2,38.1
  rectangle net VBAT: 11.8,43.8 13.1,45.9
  pour cut-out: 9.011,9.455 9.011,6.406 11.608,6.406 11.608,9.416
  pour cut-out: 2.45,9.548 2.45,6.5 5.046,6.5 5.046,9.51
  pour cut-out: 10.377,44.125 10.377,42.743 10.86,42.26 13.45,42.26 13.45,44.102

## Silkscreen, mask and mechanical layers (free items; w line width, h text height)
Top Overlay:
  drawing of 3140 lines, arcs and shapes, not listed
  text "GND" at -1.74,93.24 h0.5
  text "+3V3" at -0.58,93.23 h0.5
  text "B" at 5,84.6 h1
  text "R" at 6.45,84.55 h1
  text "G" at 7.75,79.9 h1
  text "STUDENT" at 3.963,77.01 h1
  text "TIE 2018" at 10.169,76.97 h1
  text "PITEȘTI" at 10.319,75.97 h1
  text "NAME" at 3.963,75.81 h1
  text "VBAT" at 11.76,42.08 h0.5
  text "GND" at 11.78,40.41 h0.5
Top Solder:
  rectangle: -3,93.687 10.34,95.9
Drill Guide:
  pour cut-out: 5.653,5.496 8.385,5.496 8.385,6.05 5.683,6.05
  pour cut-out: -0.137,93.38 -0.137,93.684 0.137,93.684 0.137,93.38
  pour cut-out: 11.607,46.335 11.755,46.335 11.755,46.655 11.558,46.611
M1.Outline:
  the board outline again, w0.2
M2.Dim:
  circle w0.2: c0,0 r1
  lines w0.05: 2.1,4.85 11.9,4.85 11.9,9.15 2.1,9.15 2.1,4.85
  lines w0.1: -7.4,1.1 -1.25,1.1 -0.1,0.1 ; -5.5,32 -4.5,32 ; -4,32 -3,32 ; -1,0 1,0 ; -1,32 0,32 ; -0.4,0.15 -0.1,0.1 ; -0.15,0.4 -0.1,0.1 ; 0,-1 0,0.95 ; 0,-0.025 11.3,-0.05 ; 1,32 2,32 ; 2.5,32 3.5,32 ; 3.3,74 4.3,74 ; 3.5,52 4.5,52 ; 4,32 5,32 ; 4.8,74 5.8,74 ; 5,52 6,52 ; 5.25,82 6.75,82 ; 5.5,32 6.5,32 ; 6,81.3 6,82.8 ; 6.3,74 7.3,74 ; 6.45,7.05 7.45,7.05 ; 6.5,52 7.5,52 ; 6.95,6.6 6.95,7.55 ; 7.5,32 8.5,32 ; 7.8,74 8.8,74 ; 8,52 9,52 ; 9,32 10,32 ; 10.5,32 11.5,32 ; 12,32 13,32 ; 15,41.3 15,42.3 ; 15,42.8 15,43.8 ; 15,44.3 15,45.3 ; 15,45.8 15,46.8 ; 15,76.6 15,77.6 ; 15,78.1 15,79.1 ; 15,79.6 15,80.6 ; 15,81.1 15,82.1 ; 15,83.1 15,84.1 ; 15,84.6 15,85.6 ; 15,86.1 15,87.1 ; 15,87.6 15,88.6 ; 15,89.55 15,90.55 ; 15,91.05 15,92.05 ; 15,92.55 15,93.55 ; 19.45,90.05 20.45,90.05 ; 19.55,80 20.55,80 ; 19.95,89.6 19.95,90.55 ; 20.05,79.55 20.05,80.5 ; 22.2,93.586 22.624,94.01
  lines w0.2: 10,81.25 ccw(c11,81.25) 12,81.25 12,82.75 ccw(c11,82.75) 10,82.75 10,81.25 ; 10.25,-1 cw(c10.25,0) 10.25,1 11.75,1 cw(c11.75,0) 11.75,-1 10.25,-1 ; 18.726,88.765 21.226,88.765 21.226,91.3 18.726,91.3 18.726,88.765 ; 18.8,78.7 21.335,78.7 21.335,81.2 18.8,81.2 18.8,78.7
  text "PB300" at 18.85,91.55 h0.8
  text "RIGID AREA B" at -0.55,90.15 h2
  text "x=20" at 19.017,87.823 h0.8
  text "y=90" at 19.067,87.05 h0.8
  text "LED" at 4.77,84.89 h0.8
  text "RGB" at 4.72,84.02 h0.8
  text "X=9mm" at 1.65,82.85 h0.8
  text "y=85mm" at 1.7,82 h0.8
  text "PB301" at 18.9,81.55 h0.8
  text "FLEX D" at 17.6,80.55 h3 r90
  text "#C" at 10.45,79.25 h0.8
  text "x=20" at 19.1,77.837 h0.8
  text "y=80" at 19.15,77.087 h0.8
  text "FLEX B" at 7.36,60.29 h3 r90
  text "FLEX C" at 19.407,45.4 h2
  text "NTC AREA" at 21.25,41.75 h1
  text "RIGID AREA A" at 0.2,35.35 h3 r45
  text "FLEX A" at 1.44,18.51 h3
  text "X=7mm" at 6.55,10.61 h1.2
  text "DCM03" at 2.9,9.7 h1
  text "y=7mm" at 6.55,9.42 h1.2
  text "ORIGIN" at -7.5,3.7 h1.5
  text "X=0, Y=0" at -7.55,1.35 h1.5
  text "#A" at 0.4,-1.8 h0.8
  text "#B" at 10.75,-1.9 h0.8

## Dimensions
0,0 to -2,-3 on M2.Dim
28,40 to 28,48 on M2.Dim
9.5,74 to 15,74 on M2.Dim
-3,74 to 2.5,74 on M2.Dim
23,94 to 23,76 on M2.Dim
15,74 to 15,76 on M2.Dim
15,94 to 23,94 on M2.Dim
-3,74 to -3,96 on M2.Dim
2.5,52 to -3,74 on M2.Dim
-3,32 to -3,52 on M2.Dim
2.5,52 to 9.5,52 on M2.Dim
-3,52 to 2.5,52 on M2.Dim
9.5,52 to 15,52 on M2.Dim
15,48 to 28,48 on M2.Dim
15,40 to 15,32 on M2.Dim
14,32 to 15,32 on M2.Dim
-3,32 to -2,32 on M2.Dim
0,0 to -2,-3 on M2.Dim
-2,32 to -2,-3 on M2.Dim
9.25,0 to 0,0.1 on M2.Dim
10.25,1 to 10.25,-1 on M2.Dim
9.25,0 to 12.75,0 on M2.Dim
